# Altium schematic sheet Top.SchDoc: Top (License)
size B; Date: 3/12/2014; Engineer: David McCoy (Cospan Design); DocumentNumber: 1; Revision: A; SheetNumber: 1; SheetTotal: 10
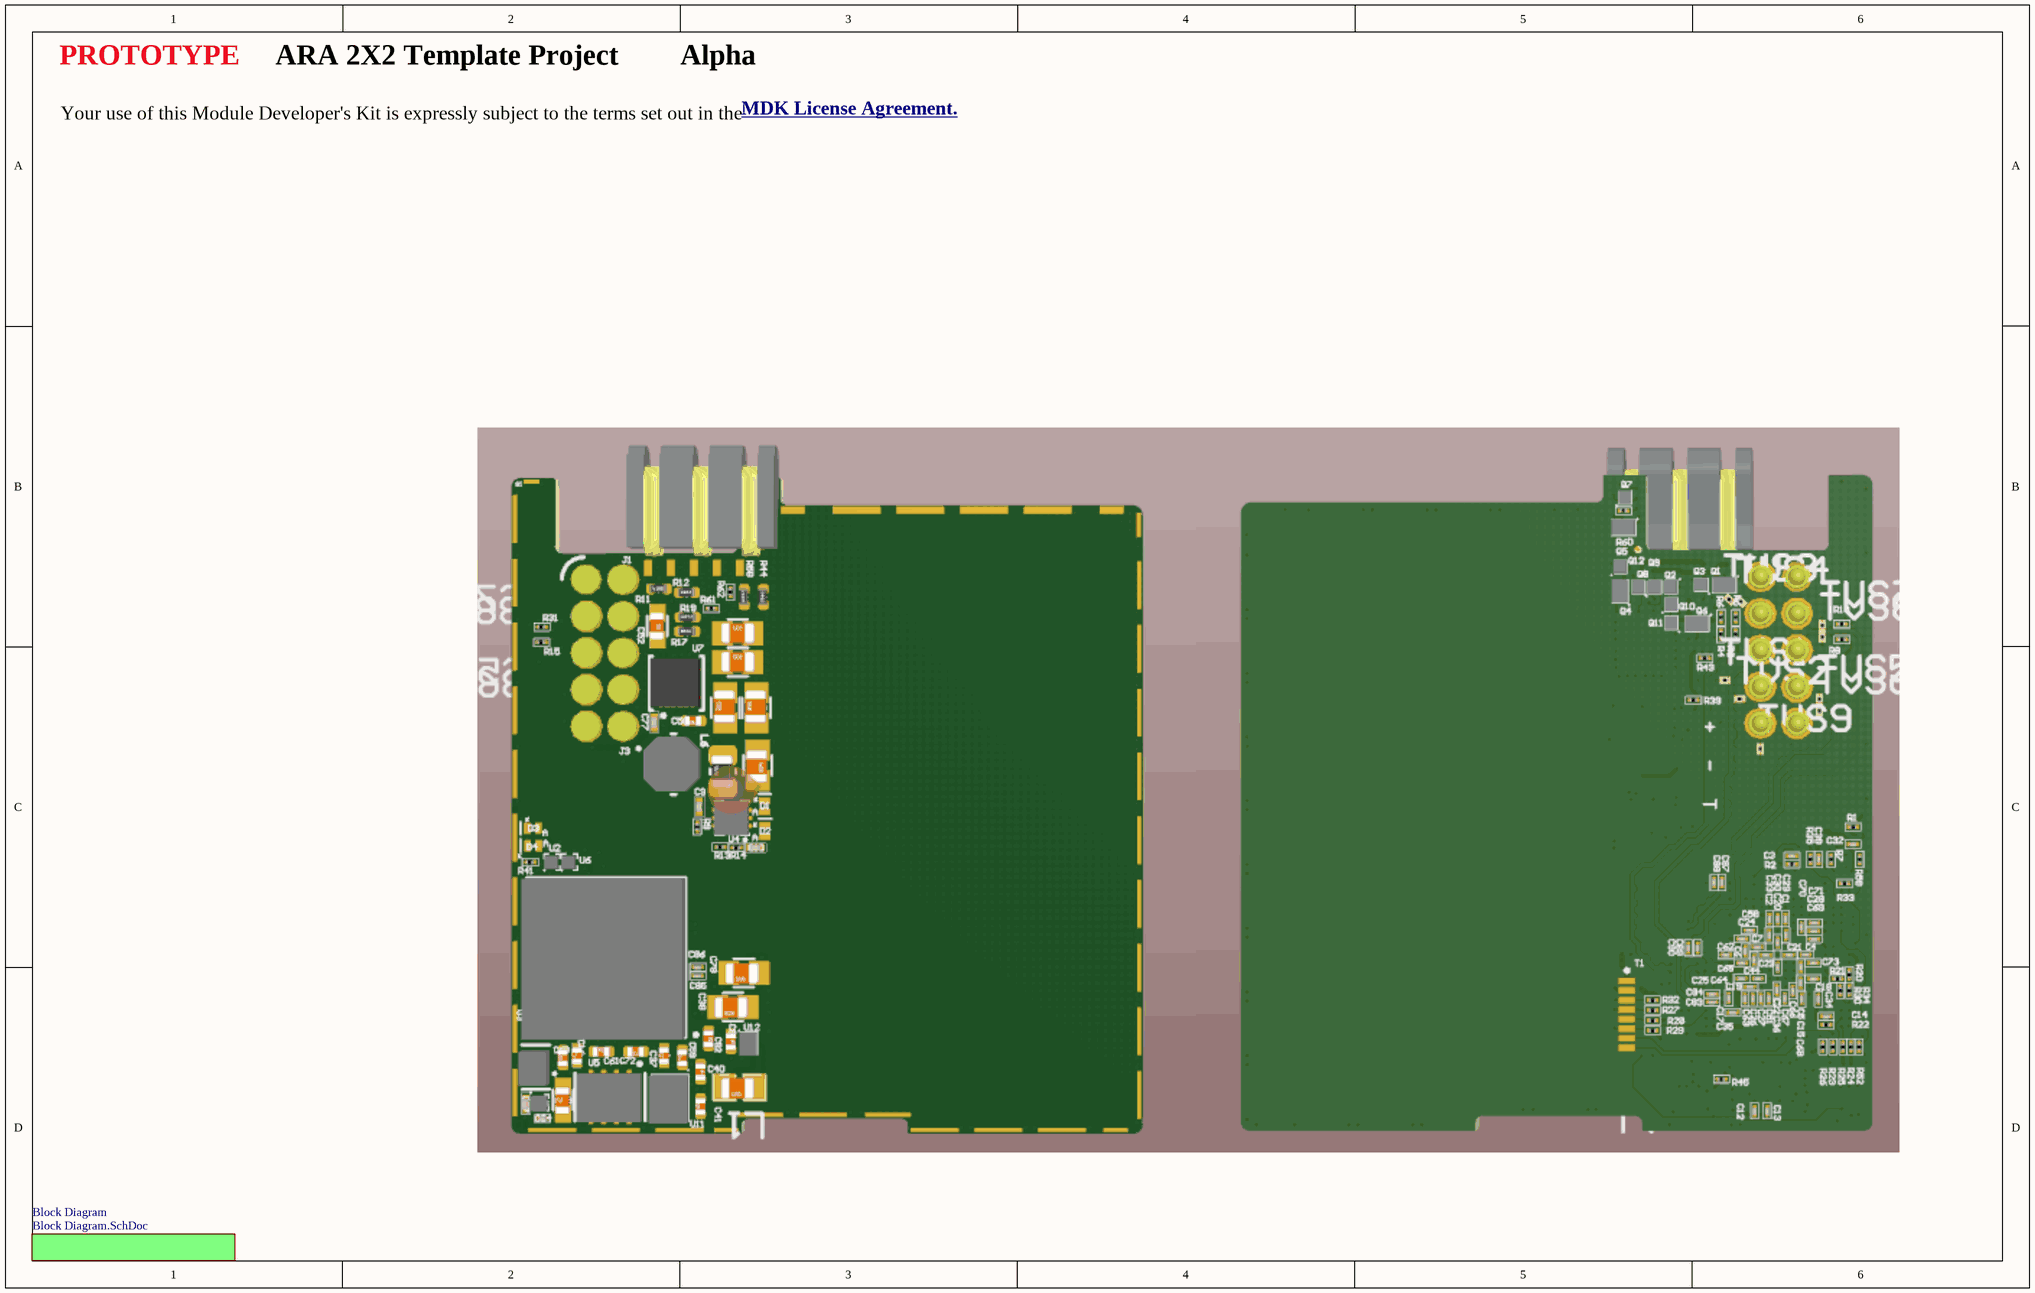
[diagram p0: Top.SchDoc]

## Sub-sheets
Block Diagram = Block Diagram.SchDoc: no entries

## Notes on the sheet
- PROTOTYPE
- ARA 2X2 Template Project
- Alpha
- Your use of this Module Developer's Kit is expressly subject to the terms set out in the
- MDK License Agreement. <http://www.projectara.com/mdk-license.txt>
